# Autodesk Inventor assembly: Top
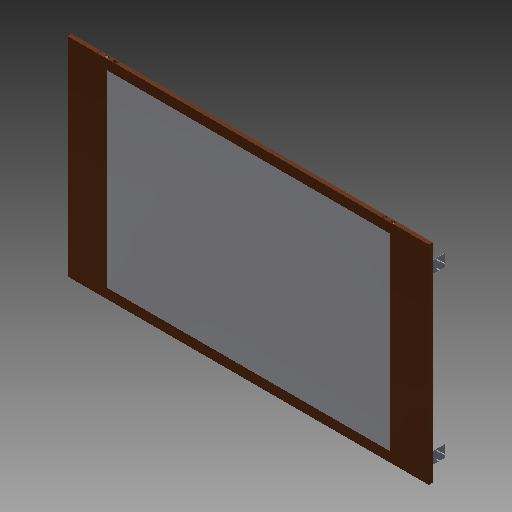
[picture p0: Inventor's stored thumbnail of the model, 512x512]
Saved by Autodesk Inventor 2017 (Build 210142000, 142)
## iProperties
Created: 2017-05
Part Number: Top
Document SubType Name: Assembly
Designer: Savy
Author: Savy
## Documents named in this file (10)
- D:\Users\Savy\Documents\Infinity Table\Top.iam
- D:\Users\Savy\Documents\Infinity Table\OneWayAcrylic.ipt
- D:\Users\Savy\Documents\Infinity Table\TopSidePanel_Long.ipt
- D:\Users\Savy\Documents\Infinity Table\TopSidePanel_Short.ipt
- D:\Users\Savy\Documents\Infinity Table\TopCutout_Cover.ipt
- D:\Users\Savy\Documents\Infinity Table\8_Screw_1inch.ipt
- D:\Users\Savy\Documents\Infinity Table\17715A430_BRACKET_step.ipt
- D:\Users\Savy\Documents\Infinity Table\TopGlass.ipt
- D:\Users\Savy\Documents\Infinity Table\8_Screw_-5inch.ipt
- D:\Users\Savy\Documents\Infinity Table\TapeStrip.ipt
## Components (48 placed, 48 different names)
1. OneWayAcrylic_1291
2. TopSidePanel_Long_1292
3. TopSidePanel_Short_1293
4. TopSidePanel_Short_1294
5. TopSidePanel_Long_1295
6. TopCutout_Cover_1296
7. 8_Screw_1inch_1297
8. 8_Screw_1inch_1298
9. 8_Screw_1inch_1299
10. 8_Screw_1inch_1300
11. 8_Screw_1inch_1301
12. 8_Screw_1inch_1302
13. 8_Screw_1inch_1303
14. 8_Screw_1inch_1304
15. 17715A430_BRACKET_step_1305
16. 17715A430_BRACKET_step_1306
17. 17715A430_BRACKET_step_1307
18. 17715A430_BRACKET_step_1308
19. TopCutout_Cover_1309
20. TopGlass_1310
21. 8_Screw_-5inch_1311
22. 8_Screw_-5inch_1312
23. 8_Screw_-5inch_1313
24. 8_Screw_-5inch_1314
25. 8_Screw_-5inch_1315
26. 8_Screw_-5inch_1316
27. 8_Screw_-5inch_1317
28. 8_Screw_-5inch_1318
29. 8_Screw_-5inch_1319
30. 8_Screw_-5inch_1320
31. 8_Screw_-5inch_1321
32. 8_Screw_-5inch_1322
33. 8_Screw_-5inch_1323
34. 8_Screw_-5inch_1324
35. 8_Screw_-5inch_1325
36. 8_Screw_-5inch_1326
37. 8_Screw_-5inch_1327
38. 8_Screw_-5inch_1328
39. 8_Screw_-5inch_1329
40. 8_Screw_-5inch_1330
41. 8_Screw_-5inch_1331
42. 8_Screw_-5inch_1332
43. 8_Screw_-5inch_1333
44. 8_Screw_-5inch_1334
45. TapeStrip_1335
46. TapeStrip_1336
47. TapeStrip_1337
48. TapeStrip_1338
